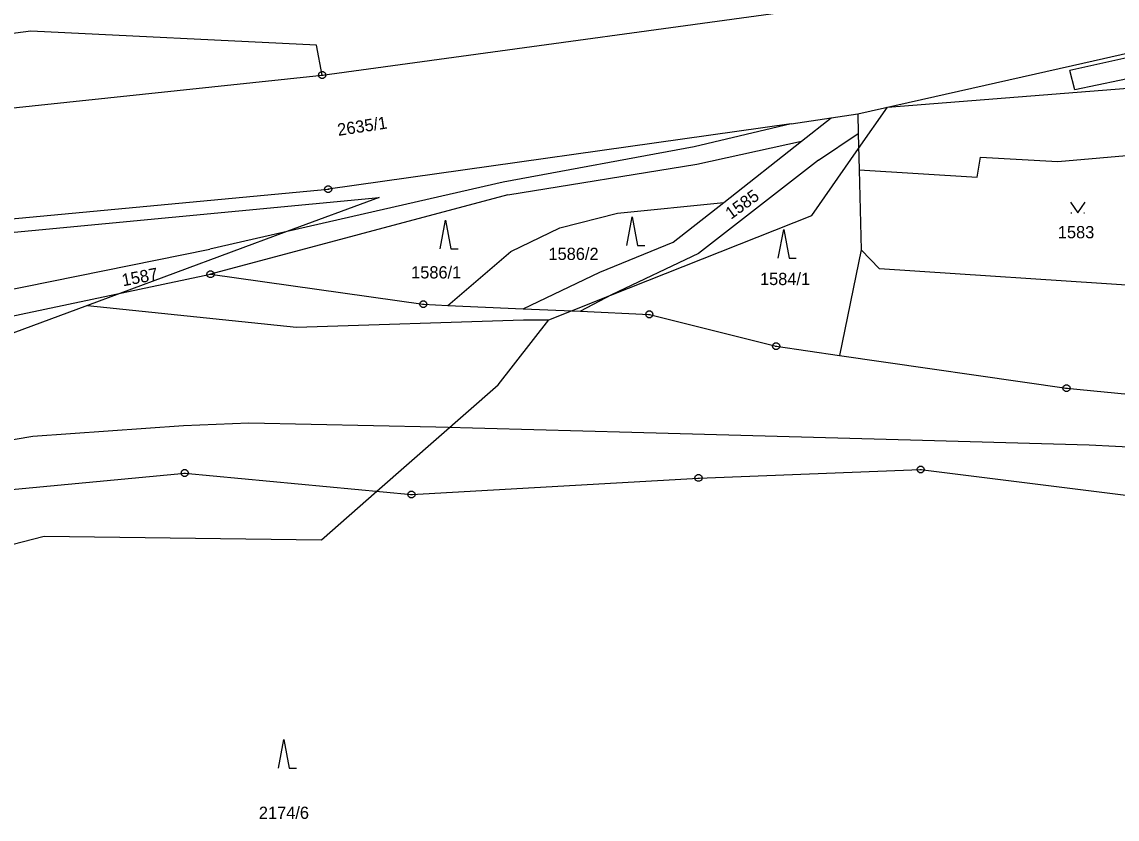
# Model space of a CAD drawing. Extents: x -806774 to -803680, y -1151731 to -1150053.
# Drawn here: x -805932.1 to -805780.2, y -1150702.3 to -1150591.7 of the extents above; entities that cross this region are included whole.
import ezdxf

# ---------------------------------------------------------------- set-up
doc = ezdxf.new("R2010")
doc.units = 0
for name, color, linetype in [('1', 7, 'Continuous'), ('11', 7, 'Continuous'), ('2', 7, 'Continuous'), ('3', 7, 'Continuous'), ('4', 7, 'Continuous'), ('6', 7, 'Continuous'), ('8', 7, 'Continuous')]:
    doc.layers.add(name, color=color, linetype=linetype)

msp = doc.modelspace()

# ---------------------------------------------------------------- linework, layer by layer
at = {"layer": '1'}
for p, q in [((-805890.43, -1150599.04), (-805797.14, -1150586.21)), ((-805930.82, -1150592.93), (-805944.13, -1150594.65)), ((-805891.22, -1150594.87), (-805930.82, -1150592.93)), ((-805890.43, -1150599.04), (-805891.22, -1150594.87)), ((-805786.36, -1150597.7), (-805774.8, -1150595.09)), ((-805816.14, -1150604.42), (-805786.36, -1150597.7)), ((-805990.21, -1150609.59), (-805890.43, -1150599.04)), ((-805825.39, -1150605.82), (-805889.59, -1150614.88)), ((-805825.39, -1150605.82), (-805838.83, -1150608.98)), ((-805825.39, -1150605.82), (-805819.83, -1150604.98)), ((-805823.93, -1150608.21), (-805819.83, -1150604.98)), ((-805819.83, -1150604.98), (-805816.14, -1150604.42)), ((-805816.14, -1150604.42), (-805816.07, -1150607.16)), ((-805821.59, -1150610.86), (-805816.07, -1150607.16)), ((-805816.07, -1150607.16), (-805815.94, -1150612.17)), ((-805838.44, -1150611.4), (-805823.93, -1150608.21)), ((-805834.72, -1150616.72), (-805823.93, -1150608.21)), ((-805838.83, -1150608.98), (-805865.32, -1150613.87)), ((-805788.39, -1150611.01), (-805766.99, -1150609.13)), ((-805864.66, -1150615.66), (-805838.44, -1150611.4)), ((-805821.59, -1150610.86), (-805838.24, -1150623.79)), ((-805799.59, -1150613.21), (-805799.09, -1150610.41)), ((-805799.09, -1150610.41), (-805788.39, -1150611.01)), ((-805815.94, -1150612.17), (-805815.66, -1150623.29)), ((-805815.94, -1150612.17), (-805799.59, -1150613.21)), ((-805991.42, -1150624.34), (-805889.59, -1150614.88)), ((-805865.32, -1150613.87), (-805906.01, -1150623.2)), ((-805864.66, -1150615.66), (-805905.92, -1150626.68)), ((-805849.46, -1150618.19), (-805834.72, -1150616.72)), ((-805841.72, -1150622.24), (-805834.72, -1150616.72)), ((-805857.48, -1150620.23), (-805849.46, -1150618.19)), ((-805864.24, -1150623.53), (-805857.48, -1150620.23)), ((-805851.91, -1150626.36), (-805841.72, -1150622.24)), ((-805955.67, -1150633.22), (-805906.01, -1150623.2)), ((-805873.01, -1150630.99), (-805864.24, -1150623.53)), ((-805838.24, -1150623.79), (-805850.31, -1150629.54)), ((-805815.66, -1150623.29), (-805818.65, -1150637.92)), ((-805813.14, -1150625.94), (-805815.66, -1150623.29)), ((-805936.34, -1150633.1), (-805905.92, -1150626.68)), ((-805905.92, -1150626.68), (-805876.4, -1150630.84)), ((-805862.56, -1150631.46), (-805851.91, -1150626.36)), ((-805755.61, -1150629.72), (-805813.14, -1150625.94)), ((-805850.31, -1150629.54), (-805854.6, -1150631.81)), ((-805876.4, -1150630.84), (-805873.01, -1150630.99)), ((-805873.01, -1150630.99), (-805862.56, -1150631.46)), ((-805862.56, -1150631.46), (-805854.6, -1150631.81)), ((-805854.6, -1150631.81), (-805845.04, -1150632.24)), ((-805845.04, -1150632.24), (-805827.46, -1150636.65)), ((-805827.46, -1150636.65), (-805818.65, -1150637.92)), ((-805818.65, -1150637.92), (-805787.18, -1150642.48)), ((-805787.18, -1150642.48), (-805727.67, -1150648.26)), ((-805944.43, -1150657.58), (-805909.49, -1150654.26)), ((-805909.49, -1150654.26), (-805878.04, -1150657.24)), ((-805838.22, -1150654.94), (-805807.41, -1150653.77)), ((-805807.41, -1150653.77), (-805769.65, -1150658.51)), ((-805878.04, -1150657.24), (-805838.22, -1150654.94))]:
    msp.add_line(p, q, dxfattribs=at)
at = {"layer": '11'}
for points in [[(-805859, -1150633), (-805855.86, -1150631.75), (-805850.37, -1150629.57), (-805822.5, -1150618.5), (-805816.02, -1150609.24), (-805812, -1150603.5), (-805774, -1150600.5)], [(-805940, -1150621.5), (-805882.5, -1150616), (-805895.32, -1150620.75), (-805918.51, -1150629.34), (-805923, -1150631)], [(-805923, -1150631), (-805950, -1150641), (-805992.5, -1150661.5), (-806028.5, -1150672), (-806043.98, -1150675.01)], [(-805923, -1150631), (-805894, -1150634), (-805862.5, -1150633), (-805859, -1150633)], [(-805942.5, -1150666.5), (-805929, -1150663), (-805890.5, -1150663.5), (-805882.85, -1150656.78), (-805866, -1150642), (-805859, -1150633)]]:
    msp.add_lwpolyline(points, dxfattribs=at)
at = {"layer": '3'}
for p, q in [((-805786.56, -1150618.16), (-805786.46, -1150618.16)), ((-805784.76, -1150618.16), (-805784.66, -1150618.16))]:
    msp.add_line(p, q, dxfattribs=at)
for points in [[(-805786.61, -1150616.66), (-805785.61, -1150618.16), (-805784.61, -1150616.66)], [(-805874.08, -1150623.16), (-805873.33, -1150619.16), (-805872.58, -1150623.16), (-805871.58, -1150623.16)], [(-805848.18, -1150622.69), (-805847.43, -1150618.69), (-805846.68, -1150622.69), (-805845.68, -1150622.69)], [(-805827.16, -1150624.44), (-805826.41, -1150620.44), (-805825.66, -1150624.44), (-805824.66, -1150624.44)], [(-805896.5, -1150695.22), (-805895.75, -1150691.22), (-805895, -1150695.22), (-805894, -1150695.22)]]:
    msp.add_lwpolyline(points, dxfattribs=at)
at = {"layer": '4'}
for p, q in [((-805775.36, -1150595.88), (-805786.72, -1150598.39)), ((-805786.04, -1150601.08), (-805786.72, -1150598.39)), ((-805774.83, -1150598.73), (-805786.04, -1150601.08))]:
    msp.add_line(p, q, dxfattribs=at)
at = {"layer": '6'}
for p, q in [((-805930.55, -1150649.15), (-805909.67, -1150647.66)), ((-805909.67, -1150647.66), (-805900.61, -1150647.28)), ((-805900.61, -1150647.28), (-805874.65, -1150647.83)), ((-805874.65, -1150647.83), (-805847.46, -1150648.58)), ((-805959.35, -1150653.87), (-805930.55, -1150649.15)), ((-805847.46, -1150648.58), (-805807.16, -1150649.69)), ((-805807.16, -1150649.69), (-805784.05, -1150650.35)), ((-805784.05, -1150650.35), (-805744.65, -1150652.17))]:
    msp.add_line(p, q, dxfattribs=at)
at = {"layer": '8'}
for p, q in [((-805890.55, -1150599.04), (-805890.31, -1150599.04)), ((-805889.71, -1150614.88), (-805889.47, -1150614.88)), ((-805906.04, -1150626.68), (-805905.8, -1150626.68)), ((-805876.52, -1150630.84), (-805876.28, -1150630.84)), ((-805845.16, -1150632.24), (-805844.92, -1150632.24)), ((-805827.58, -1150636.65), (-805827.34, -1150636.65)), ((-805787.3, -1150642.48), (-805787.06, -1150642.48)), ((-805909.61, -1150654.26), (-805909.37, -1150654.26)), ((-805807.53, -1150653.77), (-805807.29, -1150653.77)), ((-805838.34, -1150654.94), (-805838.1, -1150654.94)), ((-805878.16, -1150657.24), (-805877.92, -1150657.24))]:
    msp.add_line(p, q, dxfattribs=at)
for points in [[(-805890.28, -1150598.56), (-805890.03, -1150598.74), (-805889.93, -1150599.03), (-805890.03, -1150599.32), (-805890.28, -1150599.5), (-805890.59, -1150599.5), (-805890.84, -1150599.32), (-805890.94, -1150599.03), (-805890.84, -1150598.74), (-805890.59, -1150598.56)], [(-805889.44, -1150614.4), (-805889.19, -1150614.58), (-805889.09, -1150614.87), (-805889.19, -1150615.16), (-805889.44, -1150615.34), (-805889.75, -1150615.34), (-805890, -1150615.16), (-805890.1, -1150614.87), (-805890, -1150614.58), (-805889.75, -1150614.4)], [(-805905.77, -1150626.2), (-805905.52, -1150626.38), (-805905.42, -1150626.67), (-805905.52, -1150626.96), (-805905.77, -1150627.14), (-805906.08, -1150627.14), (-805906.33, -1150626.96), (-805906.43, -1150626.67), (-805906.33, -1150626.38), (-805906.08, -1150626.2)], [(-805876.25, -1150630.36), (-805876, -1150630.54), (-805875.9, -1150630.83), (-805876, -1150631.12), (-805876.25, -1150631.3), (-805876.56, -1150631.3), (-805876.81, -1150631.12), (-805876.91, -1150630.83), (-805876.81, -1150630.54), (-805876.56, -1150630.36)], [(-805844.89, -1150631.76), (-805844.64, -1150631.94), (-805844.54, -1150632.23), (-805844.64, -1150632.52), (-805844.89, -1150632.7), (-805845.2, -1150632.7), (-805845.45, -1150632.52), (-805845.55, -1150632.23), (-805845.45, -1150631.94), (-805845.2, -1150631.76)], [(-805827.31, -1150636.17), (-805827.06, -1150636.35), (-805826.96, -1150636.64), (-805827.06, -1150636.93), (-805827.31, -1150637.11), (-805827.62, -1150637.11), (-805827.87, -1150636.93), (-805827.97, -1150636.64), (-805827.87, -1150636.35), (-805827.62, -1150636.17)], [(-805787.03, -1150642), (-805786.78, -1150642.18), (-805786.68, -1150642.47), (-805786.78, -1150642.76), (-805787.03, -1150642.94), (-805787.34, -1150642.94), (-805787.59, -1150642.76), (-805787.69, -1150642.47), (-805787.59, -1150642.18), (-805787.34, -1150642)], [(-805909.34, -1150653.78), (-805909.09, -1150653.96), (-805908.99, -1150654.25), (-805909.09, -1150654.54), (-805909.34, -1150654.72), (-805909.65, -1150654.72), (-805909.9, -1150654.54), (-805910, -1150654.25), (-805909.9, -1150653.96), (-805909.65, -1150653.78)], [(-805807.26, -1150653.29), (-805807.01, -1150653.47), (-805806.91, -1150653.76), (-805807.01, -1150654.05), (-805807.26, -1150654.23), (-805807.57, -1150654.23), (-805807.82, -1150654.05), (-805807.92, -1150653.76), (-805807.82, -1150653.47), (-805807.57, -1150653.29)], [(-805838.07, -1150654.46), (-805837.82, -1150654.64), (-805837.72, -1150654.93), (-805837.82, -1150655.22), (-805838.07, -1150655.4), (-805838.38, -1150655.4), (-805838.63, -1150655.22), (-805838.73, -1150654.93), (-805838.63, -1150654.64), (-805838.38, -1150654.46)], [(-805877.89, -1150656.76), (-805877.64, -1150656.94), (-805877.54, -1150657.23), (-805877.64, -1150657.52), (-805877.89, -1150657.7), (-805878.2, -1150657.7), (-805878.45, -1150657.52), (-805878.55, -1150657.23), (-805878.45, -1150656.94), (-805878.2, -1150656.76)]]:
    msp.add_lwpolyline(points, close=True, dxfattribs=at)

# ---------------------------------------------------------------- texts
at = {"layer": '2'}
for s, rotation, p in [('2635/1', 8.6517, (-805888.19, -1150607.48)), ('1585', 35.9817, (-805833.73, -1150619.13)), ('1587', 10.7716, (-805918.05, -1150628.35))]:
    msp.add_text(s, height=1.7, rotation=rotation, dxfattribs=at).set_placement(p)
for s, p in [('1583', (-805788.38, -1150621.68)), ('1586/2', (-805859.04, -1150624.69)), ('1586/1', (-805878.09, -1150627.25)), ('1584/1', (-805829.7, -1150628.17)), ('2174/6', (-805899.21, -1150702.24))]:
    msp.add_text(s, height=1.7, dxfattribs=at).set_placement(p)

doc.saveas('drawing.dxf')
